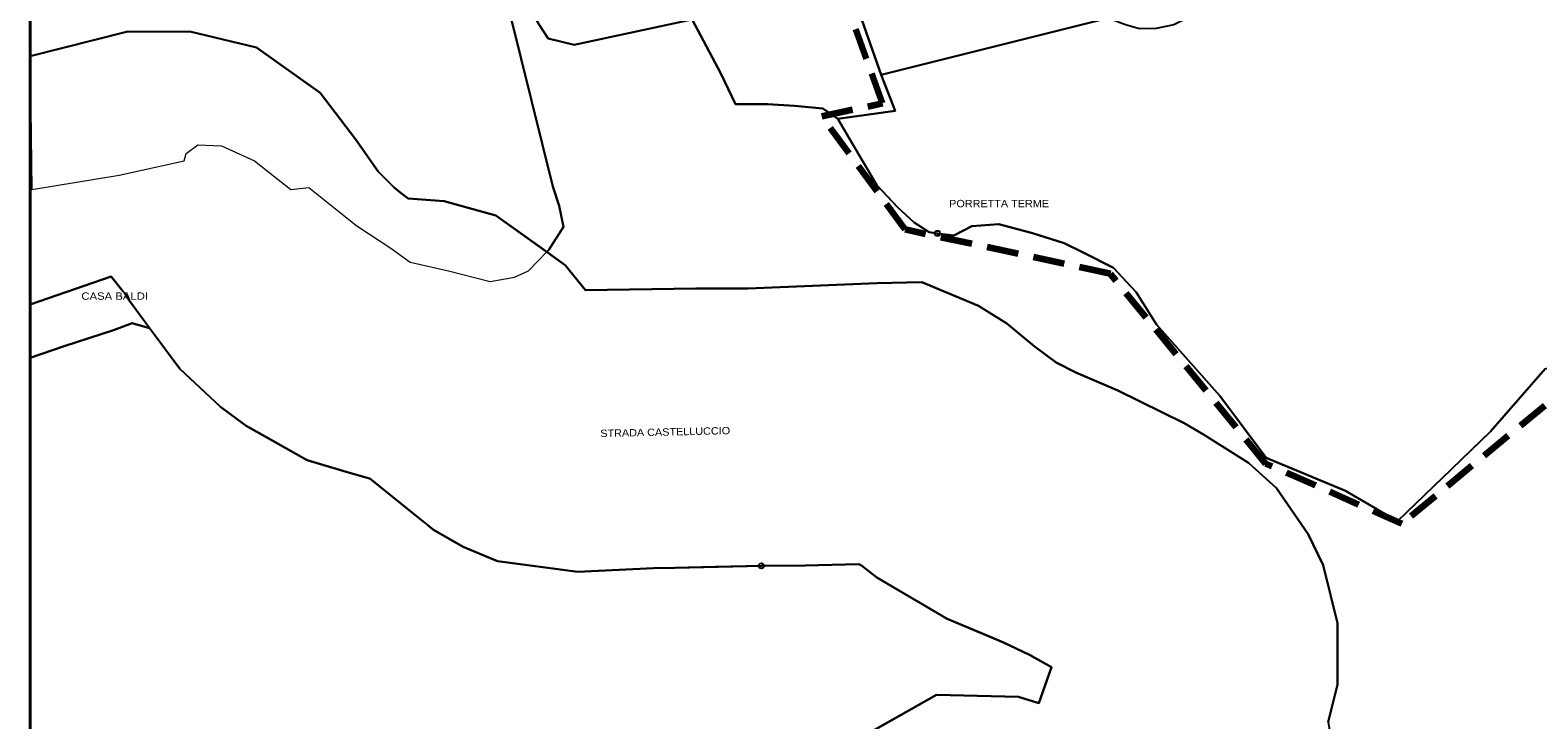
# Model space of a CAD drawing. Extents: x 654952 to 658955, y 890426 to 894481.
# Drawn here: x 657055 to 657629, y 891149 to 891411 of the extents above; entities that cross this region are included whole.
import ezdxf

# ---------------------------------------------------------------- set-up
doc = ezdxf.new("R2010")
doc.units = 0
doc.header["$LTSCALE"] = 4
doc.header["$PDMODE"] = 32
doc.header["$PDSIZE"] = 2
doc.linetypes.add('MEDIUM_DASHED', pattern=[4.5, 3, -1.5])
for name, color, linetype, lineweight in [('17', 7, 'Continuous', 25), ('32', 7, 'Continuous', 25), ('35', 7, 'Continuous', 25), ('36', 7, 'Continuous', 25), ('37', 7, 'Continuous', 25), ('56', 7, 'Continuous', 25), ('60', 7, 'Continuous', 35), ('7', 7, 'MEDIUM_DASHED', 100)]:
    doc.layers.add(name, color=color, linetype=linetype, lineweight=lineweight)
doc.layers.add('58', color=7, linetype='Continuous')

msp = doc.modelspace()

# ---------------------------------------------------------------- linework, layer by layer
at = {"layer": '17'}
for points in [[(657502.32, 891450.02), (657501.58, 891441.87), (657500.7, 891426.32), (657499.1, 891421.08), (657497.41, 891417.57), (657493.9, 891414.91), (657490.61, 891413.25), (657483.89, 891411.8), (657477.48, 891411.73), (657472.18, 891413.29), (657465.47, 891415.8), (657379.19, 891394.2)], [(657379.19, 891394.2), (657384.53, 891380.53), (657362.68, 891377.47)], [(657362.68, 891377.47), (657367.05, 891370.06), (657377.5, 891352.16), (657385.46, 891343.69), (657391.74, 891338.02), (657397.47, 891334.23), (657400.63, 891333.83)], [(657400.63, 891333.83), (657406.84, 891333.05), (657413.69, 891336.55), (657424.01, 891337.34), (657436.78, 891333.92), (657448.79, 891330.05), (657456.13, 891326.57), (657467.62, 891320.74), (657470.97, 891317.2), (657476.31, 891311.45)], [(657476.31, 891311.45), (657484.03, 891299.06), (657508.15, 891271.94)], [(657596.3, 891243.96), (657611.19, 891258.39), (657631.96, 891282.25), (657666.91, 891290.65), (657700.64, 891287.28), (657738.71, 891281.98), (657786.67, 891277.37), (657792.59, 891283.23)], [(657508.15, 891271.94), (657525.76, 891248.35), (657555.94, 891235.72), (657575.71, 891224.24), (657596.3, 891243.96)]]:
    msp.add_lwpolyline(points, dxfattribs=at)
msp.add_point((657400.63, 891333.83), dxfattribs=at)
at = {"layer": '32'}
for points in [[(657393.37, 891445.28), (657394.07, 891435.22), (657386.64, 891435.1), (657365.15, 891434.49), (657379.19, 891394.2)], [(657379.19, 891394.2), (657465.47, 891415.8), (657462.51, 891425.34), (657461.51, 891428.49), (657460.88, 891431.76), (657460.58, 891437), (657460.39, 891441.67), (657460.21, 891442.85), (657460.49, 891444.17), (657393.37, 891445.28)]]:
    msp.add_lwpolyline(points, dxfattribs=at)
at = {"layer": '35'}
for points in [[(657200.46, 891482.72), (657184.92, 891481.56), (657160.66, 891475.22), (657142.97, 891476.5), (657133.64, 891480.78), (657095.96, 891493.21), (657073.43, 891504.1), (657055.17, 891514.04), (657055.17, 891401.32)], [(657362.68, 891377.47), (657384.53, 891380.53), (657379.19, 891394.2), (657365.15, 891434.49), (657342.8, 891499.73), (657267.06, 891492.99), (657265.99, 891497.17), (657247.07, 891495.86), (657246.29, 891488.05)], [(657251.91, 891326.73), (657252.71, 891327.56), (657258.29, 891336.25), (657256.64, 891344.31), (657254.23, 891351.71), (657238, 891416.7), (657234.75, 891423.2), (657233.94, 891439.45)], [(657233.94, 891439.45), (657248.86, 891413.54), (657252.42, 891408.04), (657262.32, 891405.69), (657307.22, 891415.29), (657318.15, 891394.76), (657323.78, 891383.03), (657335.85, 891383.03), (657346.14, 891382.43), (657357.03, 891381.39), (657362.68, 891377.47)], [(657055.17, 891401.32), (657091.88, 891410.6), (657115.92, 891410.73), (657141.38, 891404.59), (657165.61, 891387.3), (657178.98, 891369.7), (657187.68, 891357.45), (657193.77, 891351.24), (657195.93, 891349.48), (657199.1, 891347.14), (657212.78, 891346.11), (657232.52, 891340.67), (657251.91, 891326.73)], [(657100.66, 891297.76), (657092.96, 891308.08), (657091.09, 891311.12), (657090.51, 891311.8), (657086.05, 891317.33), (657055.17, 891306.72), (657055.17, 891286.39), (657068.13, 891290.82), (657086.94, 891296.9)], [(657086.94, 891296.9), (657094.05, 891299.59), (657100.66, 891297.76)]]:
    msp.add_lwpolyline(points, dxfattribs=at)
at = {"layer": '35', "lineweight": 13}
for points in [[(657251.91, 891326.73), (657232.52, 891340.67), (657212.78, 891346.11), (657199.1, 891347.14), (657195.93, 891349.48), (657193.77, 891351.24), (657187.68, 891357.45), (657178.98, 891369.7), (657165.61, 891387.3), (657141.38, 891404.59), (657115.92, 891410.73), (657091.88, 891410.6), (657055.17, 891401.32), (657055.83, 891350.48)], [(657113.78, 891361.46), (657114.59, 891364.3), (657119.06, 891367.55), (657127.99, 891367.15), (657140.57, 891361.46)], [(657055.83, 891350.48), (657089.09, 891356.03), (657113.78, 891361.46)], [(657140.57, 891361.46), (657154.37, 891350.49), (657161.27, 891351.3), (657171.42, 891343.17), (657179.54, 891336.68), (657192.53, 891328.14), (657199.84, 891322.86), (657214.45, 891319.61), (657230.28, 891315.55), (657239.62, 891317.18), (657244.86, 891319.5), (657251.91, 891326.73)]]:
    msp.add_lwpolyline(points, dxfattribs=at)
at = {"layer": '36'}
for points in [[(657362.68, 891377.47), (657357.03, 891381.39), (657346.14, 891382.43), (657335.85, 891383.03), (657323.78, 891383.03), (657318.15, 891394.76), (657307.22, 891415.29), (657262.32, 891405.69), (657252.42, 891408.04), (657248.86, 891413.54), (657233.94, 891439.45)], [(657233.94, 891439.45), (657234.75, 891423.2), (657238, 891416.7), (657254.23, 891351.71), (657256.64, 891344.31), (657258.29, 891336.25), (657252.71, 891327.56), (657251.91, 891326.73)], [(657400.63, 891333.83), (657397.47, 891334.23), (657391.74, 891338.02), (657385.46, 891343.69), (657377.5, 891352.16), (657367.05, 891370.06), (657362.68, 891377.47)], [(657470.97, 891317.2), (657467.62, 891320.74), (657456.13, 891326.57), (657448.79, 891330.05), (657436.78, 891333.92), (657424.01, 891337.34), (657413.69, 891336.55), (657406.84, 891333.05), (657400.63, 891333.83)], [(657251.91, 891326.73), (657258.83, 891321.76), (657266.62, 891312.24), (657308.66, 891312.77), (657328.6, 891312.88), (657377.51, 891314.8)], [(657377.51, 891314.8), (657394.7, 891315.26), (657416.2, 891306.19), (657427, 891299.44), (657437.44, 891290.85), (657445.83, 891284.61), (657453.28, 891280.86), (657469.29, 891273.97), (657494.54, 891261.55), (657501.86, 891257.22), (657519.04, 891246.41), (657529.74, 891236.81), (657541.76, 891219.19), (657547.47, 891207.4), (657552.96, 891185.3), (657552.92, 891161.84), (657549.42, 891147.77), (657550.75, 891139.24), (657556.51, 891121.91), (657538.66, 891118.94)], [(657508.15, 891271.94), (657484.03, 891299.06), (657476.31, 891311.45), (657470.97, 891317.2)], [(657631.96, 891282.25), (657611.19, 891258.39), (657596.3, 891243.96)], [(657596.3, 891243.96), (657575.71, 891224.24), (657555.94, 891235.72), (657525.76, 891248.35), (657508.15, 891271.94)]]:
    msp.add_lwpolyline(points, dxfattribs=at)
msp.add_point((657400.63, 891333.83), dxfattribs=at)
at = {"layer": '37'}
msp.add_line((657333.56, 891207.17), (657316.03, 891206.76), dxfattribs=at)
for points in [[(657094.05, 891299.59), (657086.94, 891296.9), (657068.13, 891290.82), (657055.17, 891286.39), (657055.17, 891078.01)], [(657144.87, 891256.3), (657137.42, 891260.51), (657127.69, 891267.77), (657112.22, 891282.25), (657100.66, 891297.76), (657094.05, 891299.59)], [(657205.45, 891223.56), (657184.54, 891240.42), (657184.42, 891240.5), (657175.51, 891242.97), (657160.67, 891247.39), (657160.11, 891247.71), (657144.87, 891256.3)], [(657208.07, 891221.44), (657207.76, 891221.57), (657205.45, 891223.56)], [(657316.03, 891206.76), (657300.76, 891206.4), (657292.54, 891206.32), (657263.67, 891204.96), (657233.16, 891209.02), (657220.03, 891214.39), (657208.75, 891220.9), (657208.07, 891221.44)], [(657420.39, 891180.3), (657404.34, 891187.04), (657377.52, 891202.75), (657371.67, 891207.34), (657370.63, 891207.83), (657350.22, 891207.35), (657333.56, 891207.17)], [(657435.69, 891173.29), (657425.78, 891178.03), (657420.39, 891180.3)], [(657400.26, 891158.1), (657431.45, 891157.34), (657431.45, 891157.34), (657439.17, 891154.87), (657444.01, 891168.55), (657435.69, 891173.29)], [(657370.53, 891140.98), (657370.8, 891141.42), (657371.58, 891141.86), (657400.26, 891158.1)]]:
    msp.add_lwpolyline(points, dxfattribs=at)
msp.add_point((657333.56, 891207.17), dxfattribs=at)
at = {"layer": '56'}
for points in [[(657549.42, 891147.77), (657552.92, 891161.84), (657552.96, 891185.3), (657547.47, 891207.4), (657541.76, 891219.19), (657529.74, 891236.81), (657519.04, 891246.41), (657501.86, 891257.22), (657494.54, 891261.55), (657469.29, 891273.97), (657453.28, 891280.86), (657445.83, 891284.61), (657437.44, 891290.85), (657427, 891299.44), (657416.2, 891306.19), (657394.7, 891315.26), (657377.51, 891314.8), (657328.6, 891312.88), (657308.66, 891312.77), (657266.62, 891312.24), (657258.83, 891321.76), (657232.52, 891340.67), (657212.78, 891346.11), (657199.1, 891347.14), (657195.93, 891349.48), (657193.77, 891351.24), (657187.68, 891357.45), (657178.98, 891369.7), (657165.61, 891387.3), (657141.38, 891404.59), (657115.92, 891410.73), (657091.88, 891410.6), (657055.17, 891401.32)], [(657055.17, 891401.32), (657055.17, 891306.72), (657086.05, 891317.33)], [(657086.05, 891317.33), (657090.51, 891311.8), (657091.09, 891311.12), (657092.96, 891308.08), (657112.22, 891282.25), (657127.69, 891267.77), (657137.42, 891260.51), (657160.67, 891247.39), (657175.51, 891242.97), (657184.42, 891240.5), (657184.54, 891240.42), (657208.75, 891220.9), (657220.03, 891214.39), (657233.16, 891209.02), (657263.67, 891204.96), (657292.54, 891206.32), (657300.76, 891206.4), (657333.56, 891207.17), (657350.22, 891207.35), (657370.63, 891207.83), (657371.67, 891207.34), (657377.52, 891202.75), (657404.34, 891187.04), (657425.78, 891178.03), (657435.69, 891173.29), (657444.01, 891168.55), (657439.17, 891154.87), (657431.45, 891157.34), (657400.26, 891158.1), (657370.8, 891141.42)]]:
    msp.add_lwpolyline(points, dxfattribs=at)
at = {"layer": '60', "lineweight": 40}
msp.add_lwpolyline([(657055.17, 894480.74), (658955.28, 894480.74), (658955.28, 890425.88), (657055.17, 890425.88)], close=True, dxfattribs=at)
at = {"layer": '7'}
msp.add_lwpolyline([(657758.18, 891086.01), (657767.85, 891164.67), (657775.55, 891223.85), (657822.54, 891222.57), (657837.5, 891231.12), (657880.22, 891296.95), (657771.27, 891351.67), (657796.48, 891282.84), (657785.37, 891273.87), (657645.7, 891279.64), (657577.41, 891223.2), (657525.69, 891246.07), (657466.47, 891318.42), (657388.34, 891335.24), (657356.54, 891378.41), (657379.71, 891383.41), (657362.45, 891431.59), (657340.55, 891496.17), (657245.72, 891490.19), (657147.58, 891653.01), (657241.87, 891677.78), (657326.96, 891719.28)], dxfattribs=at)

# ---------------------------------------------------------------- texts
at = {"layer": '58'}
for s, width, p in [('PORRETTA TERME', 1.1, (657405.07, 891343.77)), ('CASA BALDI', 1.15, (657074.67, 891308.53))]:
    msp.add_text(s, height=2.801, dxfattribs=dict(at, width=width)).set_placement(p)
at = {"layer": '58', "width": 1.1}
msp.add_text('STRADA CASTELLUCCIO', height=2.801, rotation=1.278, dxfattribs=at).set_placement((657272.26, 891256.22))

doc.saveas('drawing.dxf')
